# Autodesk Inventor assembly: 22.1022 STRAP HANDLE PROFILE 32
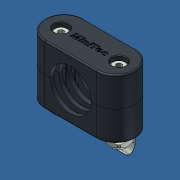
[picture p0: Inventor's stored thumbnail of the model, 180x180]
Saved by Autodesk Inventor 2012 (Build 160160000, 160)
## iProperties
Created: 2013-04
Part Number: 22.1022 STRAP HANDLE PROFILE 32
Document SubType Name: Assembly
Designer: Admin
Author: Admin
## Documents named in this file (5)
- C:\Andys Backup Data\ANDY'S INVENTOR\INVENTOR LIBRARIES\PARTS LIBRARY\KANBAN SYSTEMS\22.1022 STRAP HANDLE PROFILE 32.iam
- C:\Andys Backup Data\ANDY'S INVENTOR\INVENTOR LIBRARIES\PARTS LIBRARY\KANBAN SYSTEMS\SUBCOMPONENTS\22.1022 STRAP HANDLE 32 BOTTOM.ipt
- C:\Andys Backup Data\ANDY'S INVENTOR\INVENTOR LIBRARIES\PARTS LIBRARY\KANBAN SYSTEMS\SUBCOMPONENTS\22.1022 STRAP HANDLE 32 TOP.ipt
- C:\Andys Backup Data\ANDY'S INVENTOR\INVENTOR LIBRARIES\PARTS LIBRARY\FASTENING ELEMENTS\SCREWS CAP\21.1171 M6X50.ipt
- C:\Andys Backup Data\ANDY'S INVENTOR\INVENTOR LIBRARIES\PARTS LIBRARY\FASTENING ELEMENTS\NUTS\21.1330_2 M6 SQUARE NUT POS FXG.ipt
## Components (6 placed, 4 different names)
1. 22.1022 STRAP HANDLE 32 BOTTOM:1 — Mate:1, Mate:4, Mate:5, Angle:1, Angle:2, Mate:6, Mate:7
2. 22.1022 STRAP HANDLE 32 TOP:1 — Mate:1, Insert:1, Insert:2, Mate:7
3. 21.1171 M6X50:1 — Insert:1, Mate:2, Mate:6
4. 21.1171 M6X50:2 — Insert:2, Mate:3
5. 21.1330_2 M6 SQUARE NUT POS FXG:1 — Mate:2, Mate:5, Angle:1
6. 21.1330_2 M6 SQUARE NUT POS FXG:2 — Mate:3, Mate:4, Angle:2
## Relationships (11: Mate 7, Insert 2, Angle 2)
- Mate:1: 22.1022 STRAP HANDLE 32 BOTTOM:1 ↔ 22.1022 STRAP HANDLE 32 TOP:1
- Insert:1: 22.1022 STRAP HANDLE 32 TOP:1 ↔ 21.1171 M6X50:1
- Insert:2: 22.1022 STRAP HANDLE 32 TOP:1 ↔ 21.1171 M6X50:2
- Mate:2: 21.1171 M6X50:1 ↔ 21.1330_2 M6 SQUARE NUT POS FXG:1
- Mate:3: 21.1171 M6X50:2 ↔ 21.1330_2 M6 SQUARE NUT POS FXG:2
- Mate:4: 22.1022 STRAP HANDLE 32 BOTTOM:1 ↔ 21.1330_2 M6 SQUARE NUT POS FXG:2
- Mate:5: 22.1022 STRAP HANDLE 32 BOTTOM:1 ↔ 21.1330_2 M6 SQUARE NUT POS FXG:1
- Angle:1: 22.1022 STRAP HANDLE 32 BOTTOM:1 ↔ 21.1330_2 M6 SQUARE NUT POS FXG:1
- Angle:2: 22.1022 STRAP HANDLE 32 BOTTOM:1 ↔ 21.1330_2 M6 SQUARE NUT POS FXG:2
- Mate:6: 22.1022 STRAP HANDLE 32 BOTTOM:1 ↔ 21.1171 M6X50:1
- Mate:7: 22.1022 STRAP HANDLE 32 BOTTOM:1 ↔ 22.1022 STRAP HANDLE 32 TOP:1
